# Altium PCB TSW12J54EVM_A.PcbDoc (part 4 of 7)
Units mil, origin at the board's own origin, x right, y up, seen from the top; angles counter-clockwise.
Board outline 6301 x 2680 mil, 10 copper layers (Top Layer - L1, Gnd-Plane - L2, Signals - L3, Gnd-Plane - L4, Pwr Plane - L5, Signals - L6, Gnd-Plane - L7, Signals - L8, Gnd-Plane - L9, Bottom Layer - L10), stack 57.8 mil thick; 650 components, 374 nets, 2074 pads, 1402 vias.
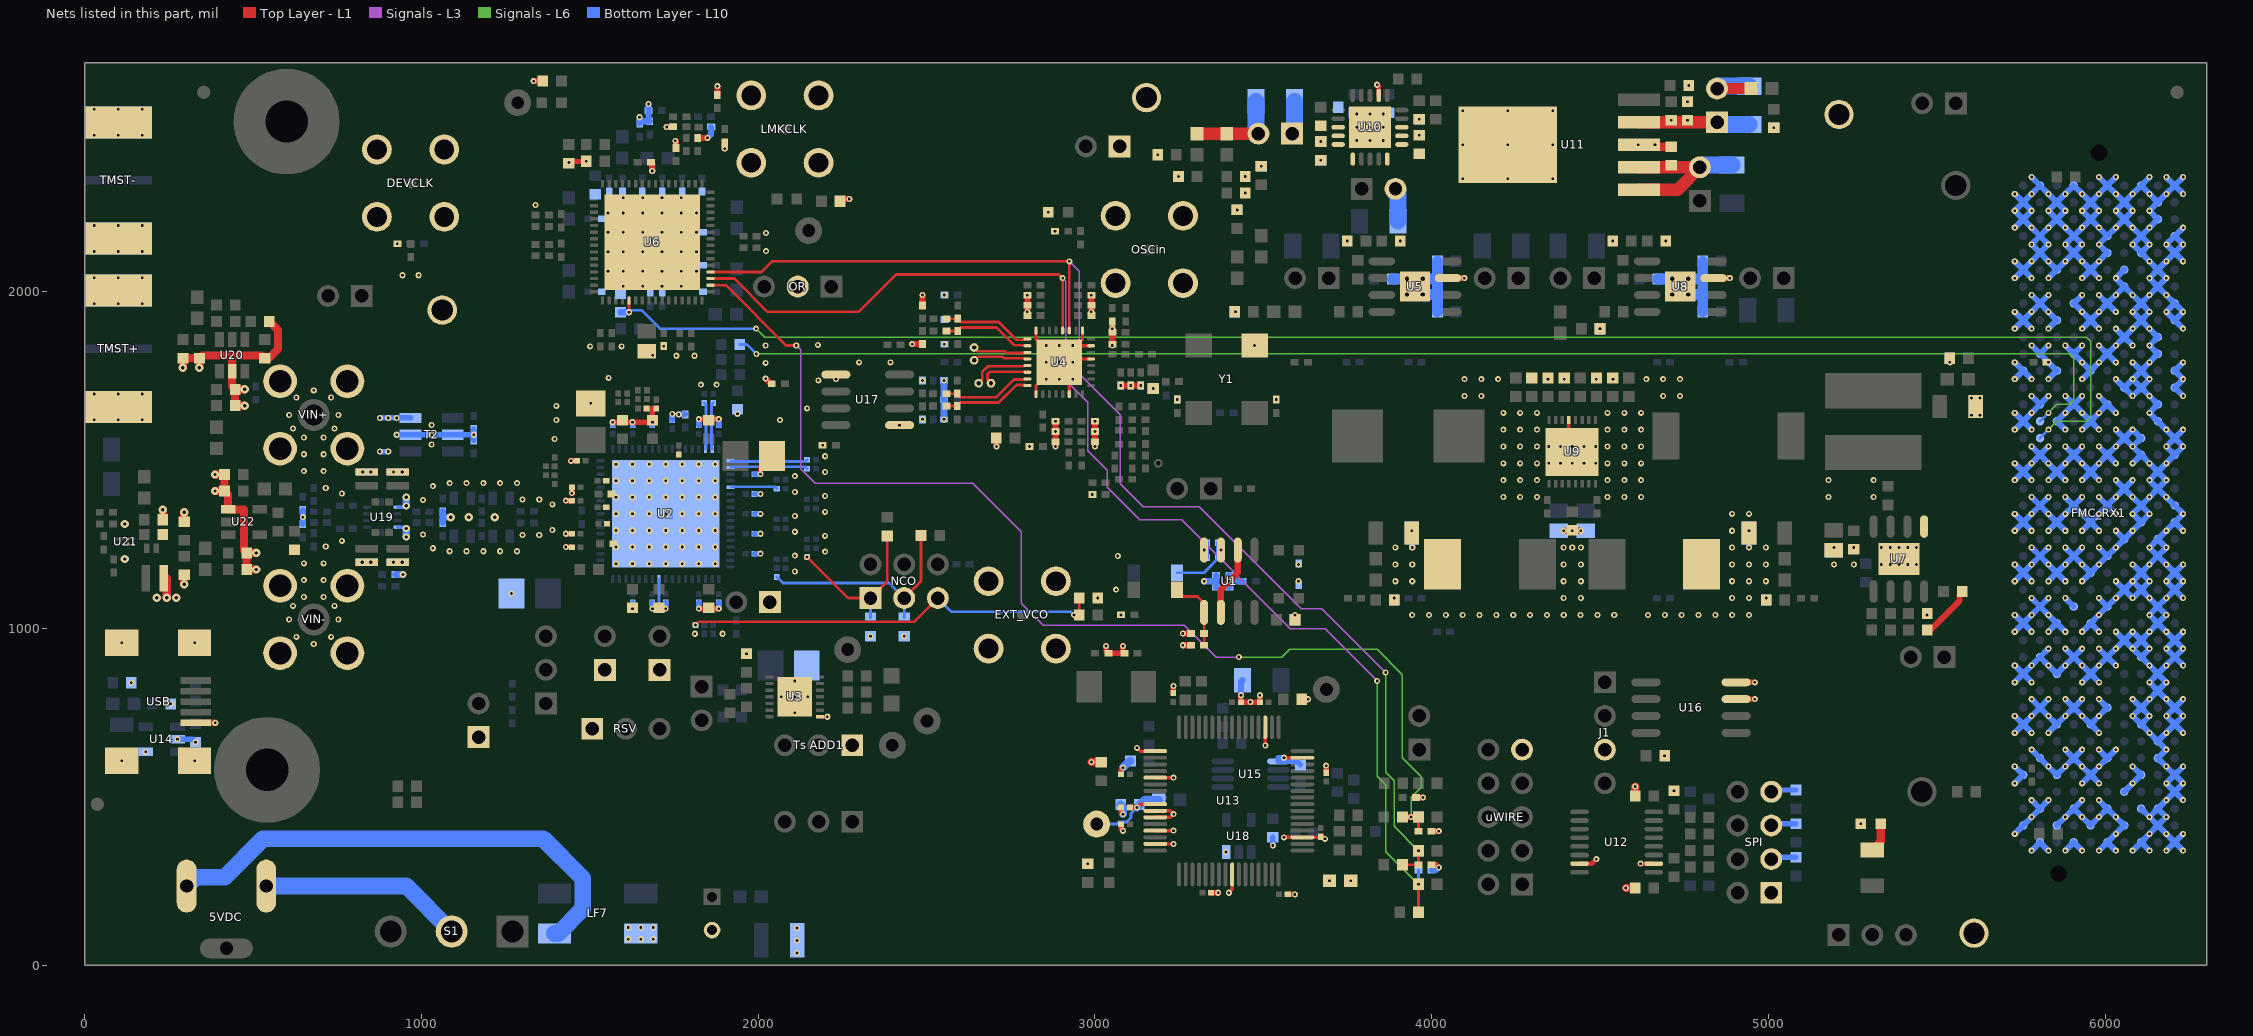
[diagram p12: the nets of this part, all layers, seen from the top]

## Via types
v1: diameter 18, hole 8, Top Layer - L1 to Bottom Layer - L10, tented both sides, 1120 vias
v2: diameter 19.68, hole 7.87, Top Layer - L1 to Bottom Layer - L10, 99 vias
v3: diameter 18, hole 8, Top Layer - L1 to Bottom Layer - L10, tented bottom, 42 vias
v4: diameter 18, hole 8, Top Layer - L1 to Bottom Layer - L10, tented top, 36 vias
v5: diameter 25, hole 10, Top Layer - L1 to Bottom Layer - L10, tented both sides, 32 vias
v6: diameter 21.46, hole 10, Top Layer - L1 to Bottom Layer - L10, tented both sides, 26 vias
v7: diameter 18, hole 8.01, Top Layer - L1 to Bottom Layer - L10, tented both sides, 16 vias
v8: diameter 18, hole 8.01, Top Layer - L1 to Bottom Layer - L10, tented bottom, 16 vias
v9: diameter 25.98, hole 12.99, Top Layer - L1 to Bottom Layer - L10, tented top, 8 vias
v10: diameter 19.68, hole 7.87, Top Layer - L1 to Bottom Layer - L10, tented top, 5 vias
v11: diameter 126, hole 106, Top Layer - L1 to Bottom Layer - L10, tented top, 2 vias

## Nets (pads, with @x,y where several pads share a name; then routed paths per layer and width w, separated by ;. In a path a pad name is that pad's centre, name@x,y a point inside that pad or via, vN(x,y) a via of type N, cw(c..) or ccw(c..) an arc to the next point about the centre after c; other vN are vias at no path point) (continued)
GND: 12V.2 "Ts ADD1.1" C2.2 C8.2 C11.2 C16.1 C18.1 C19.1 C24.2 C25.2 C27.2 C39.2 C40.2 C41.1 C42.1 C43.1 C44.1 C45.1 C46.1 C47.1 C48.2 C49.2 C50.2 C51.1 C52.1 C53.1 C54.1 C55.1 C56.1 C57.1 C58.1 C59.2 C60.2 C61.2 C62.1 C63.1 C64.1 C65.1 C66.1 C67.1 C68.1 C69.1 C70.1 C71.1 C72.2 C73.1 C74.1 C77.2 C78.2 C79.2 C80.2 C81.2 C82.2 C85.1 C88.2 C102.2 C103.2 C104.2 C105.2 C106.2 C107.2 C108.2 C109.2 C110.2 C111.2 C114.1 C115.2 C116.2 C120.2 C121.2 C122.2 C124.2 C125.2 C126.2 C127.2 C128.2 C129.2 C130.2 C143.2 C144.2 C145.2 C146.2 C147.2 C150.2 C151.2 C152.2 C153.2 C155.2 C156.1 C157.1 C158.2 C159.2 C160.2 C161.2 C162.2 C163.2 C164.2 C165.2 C166.2 C167.2 C168.2 C171.2 C172.2 C173.2 C176.2 C177.2 C178.2 C179.2 C180.2 C181.2 C182.2 C183.2 C184.2 C185.2 C186.2 C187.2 C188.2 C189.2 C190.2 C191.2 C193.2 C194.2 C195.2 C196.2 C197.2 C198.2 C199.2 C202.2 C203.2 C204.2 C206.2 C207.2 C208.2 C209.2 C213.2 C215.2 C218.2 C228.2 C229.2 C230.2 C231.1 C232.2 C233.2 C234.2 C235.1 C236.2 C237.2 C238.2 C239.2 C240.2 C241.2 C242.2 C243.2 C250.1 C251.1 C252.2 C253.2 C254.2 C255.2 C256.2 C257.2 C258.1 C259.1 C260.1 C261.2 C264.1 C265.2 C266.2 C267.1 C268.2 C269.1 C270.1 C271.2 C272.1 C276.2 C277.2 C278.2 C280.2 C281.2 C282.2 C283.2 C284.1 C285.1 C287.2 C288.2 C289.2 C290.2 C291.2 C292.1 D11.2 D12.2 DEVCLK.2 DEVCLK.3 DEVCLK.4 DEVCLK.5 EXT_Vcmo.1 EXT_VCO.2 EXT_VCO.3 EXT_VCO.4 EXT_VCO.5 FMC_RX1.A1 FMC_RX1.A4 FMC_RX1.A5 FMC_RX1.A8 FMC_RX1.A9 FMC_RX1.A12 FMC_RX1.A13 FMC_RX1.A16 FMC_RX1.A17 FMC_RX1.A20 FMC_RX1.A21 FMC_RX1.A24 FMC_RX1.A25 FMC_RX1.A28 FMC_RX1.A29 FMC_RX1.A32 FMC_RX1.A33 FMC_RX1.A36 FMC_RX1.A37 FMC_RX1.A40 FMC_RX1.B2 FMC_RX1.B3 FMC_RX1.B6 FMC_RX1.B7 FMC_RX1.B10 FMC_RX1.B11 FMC_RX1.B14 FMC_RX1.B15 FMC_RX1.B18 FMC_RX1.B19 FMC_RX1.B22 FMC_RX1.B23 FMC_RX1.B26 FMC_RX1.B27 FMC_RX1.B30 FMC_RX1.B31 FMC_RX1.B34 FMC_RX1.B35 FMC_RX1.B38 FMC_RX1.B39 FMC_RX1.C1 FMC_RX1.C4 FMC_RX1.C5 FMC_RX1.C8 FMC_RX1.C9 FMC_RX1.C12 FMC_RX1.C13 FMC_RX1.C16 FMC_RX1.C17 FMC_RX1.C20 FMC_RX1.C21 FMC_RX1.C24 FMC_RX1.C25 FMC_RX1.C28 FMC_RX1.C29 FMC_RX1.C32 FMC_RX1.C33 FMC_RX1.C36 FMC_RX1.C38 FMC_RX1.C40 FMC_RX1.D2 FMC_RX1.D3 FMC_RX1.D6 FMC_RX1.D7 FMC_RX1.D10 FMC_RX1.D13 FMC_RX1.D16 FMC_RX1.D19 FMC_RX1.D22 FMC_RX1.D25 FMC_RX1.D28 FMC_RX1.D37 FMC_RX1.D39 FMC_RX1.E1 FMC_RX1.E4 FMC_RX1.E5 FMC_RX1.E8 FMC_RX1.E11 FMC_RX1.E14 FMC_RX1.E17 FMC_RX1.E20 FMC_RX1.E23 FMC_RX1.E26 FMC_RX1.E29 FMC_RX1.E32 FMC_RX1.E35 FMC_RX1.E38 FMC_RX1.E40 FMC_RX1.F2 FMC_RX1.F3 FMC_RX1.F6 FMC_RX1.F9 FMC_RX1.F12 FMC_RX1.F15 FMC_RX1.F18 FMC_RX1.F21 FMC_RX1.F24 FMC_RX1.F27 FMC_RX1.F30 FMC_RX1.F33 FMC_RX1.F36 FMC_RX1.F39 FMC_RX1.G1 FMC_RX1.G4 FMC_RX1.G5 FMC_RX1.G8 FMC_RX1.G11 FMC_RX1.G14 FMC_RX1.G17 FMC_RX1.G20 FMC_RX1.G23 FMC_RX1.G26 FMC_RX1.G29 FMC_RX1.G32 FMC_RX1.G35 FMC_RX1.G38 FMC_RX1.G40 FMC_RX1.H2 FMC_RX1.H3 FMC_RX1.H6 FMC_RX1.H9 FMC_RX1.H12 FMC_RX1.H15 FMC_RX1.H18 FMC_RX1.H21 FMC_RX1.H24 FMC_RX1.H27 FMC_RX1.H30 FMC_RX1.H33 FMC_RX1.H36 FMC_RX1.H39 FMC_RX1.J1 FMC_RX1.J4 FMC_RX1.J5 FMC_RX1.J8 FMC_RX1.J11 FMC_RX1.J14 FMC_RX1.J17 FMC_RX1.J20 FMC_RX1.J23 FMC_RX1.J26 FMC_RX1.J29 FMC_RX1.J32 FMC_RX1.J35 FMC_RX1.J38 FMC_RX1.J40 FMC_RX1.K2 FMC_RX1.K3 FMC_RX1.K6 FMC_RX1.K9 FMC_RX1.K12 FMC_RX1.K15 FMC_RX1.K18 FMC_RX1.K21 FMC_RX1.K24 FMC_RX1.K27 FMC_RX1.K30 FMC_RX1.K33 FMC_RX1.K36 FMC_RX1.K39 GND1.1 GND2.1 GND3.1 GND.1 J1.3 L23.2 L37.2 LD.2 LF2.2 LF3.1 LF7.4 LMKCLK.2 LMKCLK.3 LMKCLK.4 LMKCLK.5 OR.2 OSCin.2 OSCin.3 OSCin.4 OSCin.5 R2.2 R3.1 R4.1 R5.1 R6.1 R10.2 R11.1 R12.1 R22.2 R23.2 R24.1 R26.1 R29.1 R30.1 R33.1 R36.1 R37.1 R45.1 R49.1 R50.2 R51.1 R56.1 R65.1 R76.1 R77.1 R86.1 R87.1 R88.1 R89.1 R90.1 R96.1 R104.1 R116.1 R122.1 R128.1 R129.1 R135.1 R139.1 R140.1 R141.1 R147.2 R152.2 R153.1 R158.1 R159.1 R165.1 R168.1 R172.1 R177.1 Ri+.1 RSV.1 SPI.1 SPI.3 SPI.5 SPI.7 T2.1 T2.2 T2.5 TMST+.2 TMST+.3 TMST+.4 TMST+.5 TMST-.2 TMST-.3 TMST-.4 TMST-.5 U1.4 U2.61 U2.69 U3.8 U3.15 U4.1 U4.8 U4.17 U4.22 U4.29 U4.31 U4.33 U5.3 U5.9 U6.65 U7.5 U7.9 U8.3 U8.9 U9.5 U9.17 U10.12 U10.21 U11.3 U11.6 U12.7 U12.10 U16.3 U16.4 U17.1 U17.5 U18.3 U19.11 U19.14 U20.2 U21.C1 U21.C2 U22.1 uWIRE.9 VA12.1 VA19.1 Vbg.1 VD12.1 VIN+.2 VIN+.3 VIN+.4 VIN+.5 VIN-.2 VIN-.3 VIN-.4 VIN-.5 Y1.2 | length 25734.7
  Top Layer - L1 w9: U3.8@2183.08,737.7 v1(2205.28,737.7)
  Top Layer - L1 w9.45: U4.17@2825.34,1695.51 2825.34,1721.1 v2(2894.24,1790) ; U4.8@2825.34,1884.49 2825.34,1858.9 v2(2894.24,1790) ; U4.33@2904.08,1799.84 U4.29@2988.72,1799.84 ; U4.22@2923.76,1695.51 U4.33@2923.76,1760.47 ; U4.33@2943.45,1839.21 U4.31@2988.72,1839.21 ; U4.1@2963.13,1884.49 2963.13,1858.9 v2(2894.24,1790)
  Top Layer - L1 w10: U9.5@4407.16,1618.49 4407.16,1553.53 U9.17@4417,1543.68
  Top Layer - L1 w11.02: v2(2894.24,1790) U4.33@2923.76,1760.47
  Top Layer - L1 w13: U12.7@4438.76,301.55 4475.03,301.55 v1(4488.48,315) ; v1(4619.68,301.55) U12.10@4659.24,301.55
  Top Layer - L1 w13.5: v1(3837.77,2614.17) 3842.27,2609.67 U10.12@3842.27,2582.49
  Top Layer - L1 w15: v1(1438.3,2383.18) 1441.86,2386.74 v1(1489.74,2386.74)
  Top Layer - L1 w16: v1(1429.03,1241.58) C51.1@1446.65,1241.57 ; v1(1429.03,1280.95) C41.1@1446.65,1280.94 ; v1(1429.03,1379.37) C42.1@1446.65,1379.37 ; v1(1444.03,1497.48) C44.1@1461.65,1497.48 ; v1(1446.65,1401.47) C54.1@1446.65,1418.74 ; v1(1567.91,1612) v1(1686.02,1612) ; R22.2@1668.99,1653 R23.2@1697,1653.01 ; v1(1686.02,1058.65) v1(1725.39,1058.65) ; C50.2@1686.02,1618.3 1686.02,1653 ; v1(1823.81,1058.65) v1(1882.87,1058.65) ; v1(1823.81,1621.35) v1(1882.87,1621.35) ; v1(2006.74,1458.11) 2006.74,1477.62 C72.2@2040.52,1511.4
  Top Layer - L1 w16.5: R116.1@3952.93,498 v1(3973.98,498) ; R128.1@3999.81,298 4012.87,298 v1(4020.87,290) ; R104.1@3999.81,398 v1(4020.87,398) ; U16.3@4903.86,790 v1(4959.16,790) ; U16.4@4903.86,840 v1(4959.16,840)
  Top Layer - L1 w18: v1(1333.3,2625) R45.1@1360.94,2625 ; C85.1@1681.68,2384 1685.56,2380.13 v1(1685.56,2358.32) ; v1(1728.43,2489) R50.2@1747.3,2489 ; v1(1754.16,2447.5) 1756,2445.65 C88.2@1756,2426.69 ; C114.1@1820.67,2456.68 v1(1849.54,2456.69) ; C259.1@1878.91,2584.24 v1(1878.91,2610.11) ; v1(1900.67,2424.26) R51.1@1900.67,2443.13 ; v1(2022.36,1741.48) 2037.84,1726 C215.2@2040.31,1726 ; v1(2230.84,1740) U17.5@2230.84,1753.5 ; R56.1@2243.06,2274.95 v1(2270.7,2274.95) ; v1(2457.23,1843.81) R36.1@2488.05,1843.81 ; R29.1@2488.05,1959.18 v1(2488.05,1990) ; v1(2707.44,1540) R152.2@2707.44,1565 ; C257.2@2799.35,1929.09 C256.2@2799.35,1959.09 v1(2799.35,1989.09) ; v1(2882.55,1540) C243.2@2882.55,1554.68 v1(2882.55,1614.68) ; C254.2@2989.12,1929.09 C253.2@2989.12,1959.09 v1(2989.12,1989.09) ; v1(2999.92,1540) C240.2@2999.92,1554.68 v1(2999.92,1614.68) ; v1(3076.33,1721.1) v1(3136.33,1721.1) ; v1(3260.82,950) R11.1@3284.63,950 ; v1(3260.82,985) C8.2@3284.63,985 ; U5.3@4048.43,2040 v1(4096.8,2040) ; v1(4391.47,1290) v1(4442.53,1290) ; U8.3@4836.43,2040 v1(4884.8,2040) ; R76.1@5470.56,995 5480,995 5567,1082 5567,1101.98 C162.2@5574.56,1109.54
  Top Layer - L1 w19.68: C251.1@3051.65,1844 R30.1@3051.65,1911.41
  Top Layer - L1 w24: C282.2@232.29,1322.99 v5(232.29,1352.22) ; v5(291.99,1774.4) C280.2@291.99,1802.65 C281.2@340.99,1802.65 ; v5(295.73,1131.18) C284.1@295.73,1159.43 ; C285.1@295.73,1316.55 v5(295.73,1344.8) ; v5(340.99,1774.4) C281.2@340.99,1802.65 ; v5(387.19,1408) C289.2@415.44,1408 ; v5(387.19,1457) C290.2@415.44,1457 C289.2@415.44,1408 ; v5(475.1,1661.52) C276.2@446.85,1661.52 C277.2@446.85,1709.52 ; v5(475.1,1709.52) C277.2@446.85,1709.52 ; v5(509.44,1175) C287.2@481.19,1175 C288.2@481.19,1224 ; v5(509.44,1224) C288.2@481.19,1224 ; R172.1@548.55,1911.52 573.99,1886.08 573.99,1829.45 547.19,1802.65 C278.2@534.99,1802.65 527.12,1810.52 437.99,1810.52 ; v1(4576.37,229) R65.1@4604.12,229 ; C129.2@4604.12,502.06 v1(4604.12,530.79) ; U11.3@4615.22,2436 4621.13,2430.09 C196.2@4711,2430.09 ; C281.2@340.99,1802.65 348.87,1810.52 437.99,1810.52 ; C289.2@415.44,1408 426.07,1397.37 U22.1@426.07,1353.4 473.32,1353.4 473.32,1231.87 C288.2@481.19,1224 ; 437.99,1810.52 U20.2@437.99,1763.28 437.99,1718.38 C277.2@446.85,1709.52
  Top Layer - L1 w25: v5(243.59,1090.99) L37.2@243.59,1148.49
  Bottom Layer - L10 w9: 1705.7,1058.65 U2.61@1705.7,1147.09
  Bottom Layer - L10 w9.84: U19.14@928.89,1300.63 951.4,1300.63 v6(955.37,1296.66) ; U19.11@928.89,1359.68 951.4,1359.68 v6(955.37,1363.65)
  Bottom Layer - L10 w16: v1(876.58,1524.95) v1(901.58,1524.95) ; v1(876.58,1624.95) T2.1@968.06,1624.95 ; v1(926.58,1574.95) v1(1155.85,1574.95) ; C229.2@1155.85,1558.14 v1(1155.85,1574.95) ; C228.2@1155.85,1591.76 v1(1155.85,1574.95) ; C45.1@1567.91,1603.73 v1(1567.91,1612) ; v1(1626.96,1058.65) C47.1@1626.96,1076.27 ; C46.1@1626.96,1603.73 v1(1626.96,1612) ; C58.1@1686.01,1076.27 v1(1686.02,1058.65) v1(1725.39,1058.65) C57.1@1725.39,1076.27 ; C55.1@1686.02,1603.73 v1(1686.02,1612) ; C56.1@1745.07,1618.73 v1(1745.07,1636.35) ; v1(1764.16,1635.31) C16.1@1783,1635.31 ; v1(1823.81,1058.65) C62.1@1823.81,1076.27 ; C70.1@1823.81,1603.73 v1(1823.81,1621.35) ; v1(1882.87,1058.65) C63.1@1882.87,1076.27 ; C69.1@1882.87,1603.73 v1(1882.87,1621.35) ; C64.1@1989.12,1221.89 v1(2006.74,1221.89) ; C65.1@1989.12,1280.95 v1(2006.74,1280.94) ; C66.1@1989.12,1340 v1(2006.74,1340) ; C67.1@1989.12,1399.05 v1(2006.74,1399.05) ; C68.1@1989.12,1458.11 v1(2006.74,1458.11) ; SPI.3@5008,315 5013.12,320.12 R139.1@5081.44,320.12 ; SPI.5@5008,415 5013.12,420.12 R140.1@5081.44,420.12 ; SPI.7@5008,515 5013.12,520.12 R141.1@5081.44,520.12
  Bottom Layer - L10 w16.5: v1(3528,355.39) C213.2@3528,380.13 ; R129.1@3999.81,282 4012.87,282 v1(4020.87,290)
  Bottom Layer - L10 w18: R168.1@648,1309.35 v1(648,1330.16) Ri+.1@648,1350.97 ; C107.2@1647.92,2498.87 v1(1647.92,2517.74) ; C107.2@1647.92,2505.74 C104.2@1678.05,2505.74 1674.31,2509.47 C260.1@1674.32,2537.87 v1(1674.32,2556.74) ; v1(1728.43,2489) R159.1@1747.3,2489 ; v1(1849.54,2456.69) 1860.04,2467.19 R158.1@1860.04,2489 ; v1(3942,1240) C183.2@3942,1290 ; 4016.93,2040 v1(4096.8,2040) ; 4804.93,2040 v1(4884.8,2040) ; v1(4941.85,1240) v1(4941.85,1290) ; v1(5731,390) FMC_RX1.K39@5756,415 v1(5781,440) FMC_RX1.J38@5806,465 ; v1(5731,540) FMC_RX1.K36@5756,565 v1(5731,590) ; v1(5731,690) FMC_RX1.K33@5756,715 ; v1(5731,740) FMC_RX1.K33@5756,715 ; v1(5731,840) FMC_RX1.K30@5756,865 ; v1(5731,890) FMC_RX1.K30@5756,865 ; v1(5731,990) FMC_RX1.K27@5756,1015 ; v1(5731,1040) FMC_RX1.K27@5756,1015 ; v1(5731,1140) FMC_RX1.K24@5756,1165 ; v1(5731,1190) FMC_RX1.K24@5756,1165 ; v1(5731,1290) FMC_RX1.K21@5756,1315 ; v1(5731,1340) FMC_RX1.K21@5756,1315 ; v1(5731,1440) FMC_RX1.K18@5756,1465 ; v1(5731,1490) FMC_RX1.K18@5756,1465 ; v1(5731,1590) FMC_RX1.K15@5756,1615 ; v1(5731,1640) FMC_RX1.K15@5756,1615 ; v1(5731,1740) FMC_RX1.K12@5756,1765 ; v1(5731,1790) FMC_RX1.K12@5756,1765 ; v1(5731,1890) FMC_RX1.K9@5756,1915 ; v1(5731,1940) FMC_RX1.K9@5756,1915 ; v1(5731,2040) FMC_RX1.K6@5756,2065 ; v1(5731,2090) FMC_RX1.K6@5756,2065 ; v1(5731,2190) FMC_RX1.K3@5756,2215 ; v1(5731,2290) FMC_RX1.K2@5756,2265 ; v1(5781,340) FMC_RX1.J40@5806,365 v1(5831,340) ; v1(5781,490) FMC_RX1.J38@5806,465 ; v1(5781,640) FMC_RX1.J35@5806,615 v1(5831,590) FMC_RX1.H36@5856,565 v1(5881,590) FMC_RX1.G35@5906,615 ; v1(5781,690) FMC_RX1.K33@5756,715 ; v1(5781,790) FMC_RX1.J32@5806,765 ; v1(5781,840) FMC_RX1.K30@5756,865 ; v1(5781,990) FMC_RX1.K27@5756,1015 ; v1(5781,1090) FMC_RX1.J26@5806,1065 ; v1(5781,1140) FMC_RX1.K24@5756,1165 ; v1(5781,1240) FMC_RX1.J23@5806,1215 ; v1(5781,1290) FMC_RX1.K21@5756,1315 ; v1(5781,1390) FMC_RX1.J20@5806,1365 ; v1(5781,1440) FMC_RX1.K18@5756,1465 ; v1(5781,1540) FMC_RX1.J17@5806,1515 ; v1(5781,1590) FMC_RX1.K15@5756,1615 ; v1(5781,1690) FMC_RX1.J14@5806,1665 ; v1(5781,1740) FMC_RX1.K12@5756,1765 ; v1(5781,1840) FMC_RX1.J11@5806,1815 ; v1(5781,1890) FMC_RX1.K9@5756,1915 ; v1(5781,1990) FMC_RX1.J8@5806,1965 ; v1(5781,2040) FMC_RX1.K6@5756,2065 ; v1(5781,2340) FMC_RX1.J1@5806,2315 ; v1(5831,490) FMC_RX1.J38@5806,465 ; v1(5831,690) FMC_RX1.H33@5856,715 ; v1(5831,790) FMC_RX1.J32@5806,765 ; v1(5831,940) FMC_RX1.J29@5806,915 ; v1(5831,990) FMC_RX1.H27@5856,1015 ; v1(5831,1090) FMC_RX1.J26@5806,1065 ; v1(5831,1140) FMC_RX1.H24@5856,1165 ; v1(5831,1240) FMC_RX1.J23@5806,1215 ; v1(5831,1290) FMC_RX1.H21@5856,1315 ; v1(5831,1390) FMC_RX1.J20@5806,1365 ; v1(5831,1440) FMC_RX1.H18@5856,1465 ; v1(5831,1540) FMC_RX1.J17@5806,1515 ; v1(5831,1690) FMC_RX1.J14@5806,1665 ; v1(5831,1740) FMC_RX1.H12@5856,1765 v1(5831,1790) FMC_RX1.J11@5806,1815 ; v1(5831,1840) FMC_RX1.J11@5806,1815 ; v1(5831,1890) FMC_RX1.H9@5856,1915 v1(5831,1940) FMC_RX1.J8@5806,1965 ; v1(5831,1990) FMC_RX1.J8@5806,1965 ; v1(5831,2040) FMC_RX1.H6@5856,2065 ; FMC_RX1.H39@5856,415 v1(5881,440) FMC_RX1.G38@5906,465 ; v1(5881,340) FMC_RX1.G40@5906,365 v1(5931,340) ; v1(5881,640) FMC_RX1.G35@5906,615 ; v1(5881,790) FMC_RX1.G32@5906,765 ; v1(5881,940) FMC_RX1.G29@5906,915 ; v1(5881,990) FMC_RX1.H27@5856,1015 ; v1(5881,1090) FMC_RX1.G26@5906,1065 ; v1(5881,1140) FMC_RX1.H24@5856,1165 ; v1(5881,1240) FMC_RX1.G23@5906,1215 ; v1(5881,1290) FMC_RX1.H21@5856,1315 ; v1(5881,1390) FMC_RX1.G20@5906,1365 ; v1(5881,1440) FMC_RX1.H18@5856,1465 ; v1(5881,1540) FMC_RX1.G17@5906,1515 ; v1(5881,1590) FMC_RX1.H15@5856,1615 v1(5881,1640) FMC_RX1.G14@5906,1665 ; v1(5881,1690) FMC_RX1.G14@5906,1665 ; v1(5881,1840) FMC_RX1.G11@5906,1815 ; v1(5931,490) FMC_RX1.G38@5906,465 ; v1(5931,540) FMC_RX1.F36@5956,565 ; v1(5931,640) FMC_RX1.G35@5906,615 ; v1(5931,790) FMC_RX1.G32@5906,765 ; v1(5931,840) FMC_RX1.F30@5956,865 ; v1(5931,940) FMC_RX1.G29@5906,915 ; v1(5931,990) FMC_RX1.F27@5956,1015 ; v1(5931,1140) FMC_RX1.F24@5956,1165 ; v1(5931,1240) FMC_RX1.G23@5906,1215 ; v1(5931,1290) FMC_RX1.F21@5956,1315 ; v1(5931,1390) FMC_RX1.G20@5906,1365 ; v1(5931,1440) FMC_RX1.F18@5956,1465 ; v1(5931,1540) FMC_RX1.G17@5906,1515 ; v1(5931,1590) FMC_RX1.F15@5956,1615 ; v1(5931,1690) FMC_RX1.G14@5906,1665 ; v1(5931,1740) FMC_RX1.F12@5956,1765 ; v1(5931,1840) FMC_RX1.G11@5906,1815 ; v1(5931,1890) FMC_RX1.F9@5956,1915 ; v1(5931,1990) FMC_RX1.G8@5906,1965 v1(5931,1940) FMC_RX1.F9@5956,1915 ; v1(5931,2040) FMC_RX1.F6@5956,2065 ; FMC_RX1.F9@5954,1913 v1@5979,1938 ; v1(5981,340) FMC_RX1.E40@6006,365 ; v1(5981,490) FMC_RX1.E38@6006,465 ; v1(5981,540) FMC_RX1.F36@5956,565 ; v1(5981,640) FMC_RX1.E35@6006,615 ; v1(5981,690) FMC_RX1.F33@5956,715 ; v1(5981,790) FMC_RX1.E32@6006,765 v1(5981,740) FMC_RX1.F33@5956,715 ; v1(5981,840) FMC_RX1.F30@5956,865 ; v1(5981,940) FMC_RX1.E29@6006,915 ; v1(5981,990) FMC_RX1.F27@5956,1015 ; v1(5981,1090) FMC_RX1.E26@6006,1065 ; v1(5981,1240) FMC_RX1.E23@6006,1215 ; v1(5981,1290) FMC_RX1.F21@5956,1315 ; v1(5981,1390) FMC_RX1.E20@6006,1365 ; v1(5981,1440) FMC_RX1.F18@5956,1465 ; v1(5981,1540) FMC_RX1.E17@6006,1515 ; v1(5981,1590) FMC_RX1.F15@5956,1615 ; v1(5981,1690) FMC_RX1.E14@6006,1665 ; v1(5981,1840) FMC_RX1.E11@6006,1815 ; v1(5981,1890) FMC_RX1.F9@5956,1915 ; v1(5981,1940) FMC_RX1.E8@6006,1965 ; v1(5981,1990) FMC_RX1.E8@6006,1965 ; v1(5981,2040) FMC_RX1.F6@5956,2065 ; v1(5981,2340) FMC_RX1.E1@6006,2315 ; v1(6031,340) FMC_RX1.E40@6006,365 ; v1(6031,640) FMC_RX1.E35@6006,615 ; v1(6031,890) FMC_RX1.E29@6006,915 ; v1(6031,990) FMC_RX1.D28@6056,965 ; v1(6031,1140) FMC_RX1.D25@6056,1115 ; v1(6031,1290) FMC_RX1.D22@6056,1265 ; v1(6031,1340) FMC_RX1.E20@6006,1365 ; v1(6031,1440) FMC_RX1.D19@6056,1415 ; v1(6031,1490) FMC_RX1.E17@6006,1515 ; v1(6031,1590) FMC_RX1.D16@6056,1565 ; v1(6031,1640) FMC_RX1.E14@6006,1665 ; v1(6031,1740) FMC_RX1.D13@6056,1715 ; v1(6031,1790) FMC_RX1.E11@6006,1815 ; v1(6031,1890) FMC_RX1.D10@6056,1865 ; v1(6031,1940) FMC_RX1.E8@6006,1965 ; v1(6031,2340) FMC_RX1.E1@6006,2315 ; FMC_RX1.D37@6056,515 v1(6081,540) FMC_RX1.C36@6106,565 v1(6081,590) ; FMC_RX1.D6@6056,2065 v1(6031,2040) FMC_RX1.D7@6056,2015 ; v1(6081,340) FMC_RX1.C40@6106,365 ; v1(6081,790) FMC_RX1.C32@6106,765 ; v1(6081,1140) FMC_RX1.D25@6056,1115 ; v1(6081,1190) FMC_RX1.C24@6106,1165 ; v1(6081,1440) FMC_RX1.D19@6056,1415 ; v1(6081,1490) FMC_RX1.C17@6106,1515 ; v1(6081,1790) FMC_RX1.C12@6106,1765 ; v1(6081,1840) FMC_RX1.D10@6056,1865 ; FMC_RX1.C38@6106,465 v1(6131,440) ; FMC_RX1.C25@6107,1115 6082,1140 FMC_RX1.C24@6107,1165 ; v1(6131,340) FMC_RX1.C40@6106,365 ; v1(6131,1440) FMC_RX1.B18@6156,1465 ; v1(6131,2340) FMC_RX1.C1@6106,2315 ; v1@6135,1436 FMC_RX1.B19@6160,1411 ; v1(6181,340) FMC_RX1.A40@6206,365 ; v1(6181,2340) FMC_RX1.A1@6206,2315 ; v1(6231,340) FMC_RX1.A40@6206,365 ; v1(6231,390) FMC_RX1.A40@6206,365 ; v1(6231,490) FMC_RX1.A37@6206,515 ; v1(6231,590) FMC_RX1.A36@6206,565 ; v1(6231,690) FMC_RX1.A33@6206,715 ; v1(6231,790) FMC_RX1.A32@6206,765 ; v1(6231,890) FMC_RX1.A29@6206,915 ; v1(6231,990) FMC_RX1.A28@6206,965 ; v1(6231,1090) FMC_RX1.A25@6206,1115 ; v1(6231,1190) FMC_RX1.A24@6206,1165 ; v1(6231,1290) FMC_RX1.A21@6206,1315 ; v1(6231,1590) FMC_RX1.A16@6206,1565 ; v1(6231,1690) FMC_RX1.A13@6206,1715 v1(6231,1740) FMC_RX1.A12@6206,1765 v1(6231,1790) ; v1(6231,1890) FMC_RX1.A9@6206,1915 ; v1(6231,2090) FMC_RX1.A5@6206,2115 ; v1(6231,2190) FMC_RX1.A4@6206,2165 ; v1(6231,2290) FMC_RX1.A1@6206,2315 ; v1(6231,2340) FMC_RX1.A1@6206,2315 ; FMC_RX1.K33@5756,715 v1(5781,740) FMC_RX1.J32@5806,765 ; FMC_RX1.K30@5756,865 v1(5781,890) FMC_RX1.J29@5806,915 ; FMC_RX1.K27@5756,1015 v1(5781,1040) FMC_RX1.J26@5806,1065 ; FMC_RX1.K24@5756,1165 v1(5781,1190) FMC_RX1.J23@5806,1215 ; FMC_RX1.K21@5756,1315 v1(5781,1340) FMC_RX1.J20@5806,1365 ; FMC_RX1.K18@5756,1465 v1(5781,1490) FMC_RX1.J17@5806,1515 ; FMC_RX1.K15@5756,1615 v1(5781,1640) FMC_RX1.J14@5806,1665 ; FMC_RX1.K9@5756,1915 v1(5781,1940) FMC_RX1.J8@5806,1965 ; FMC_RX1.K6@5756,2065 v1(5781,2090) FMC_RX1.J5@5806,2115 ; FMC_RX1.K3@5756,2215 v1(5731,2240) FMC_RX1.K2@5756,2265 ; FMC_RX1.K3@5756,2215 v1(5781,2190) FMC_RX1.J4@5806,2165 ; FMC_RX1.K3@5756,2215 v1(5781,2240) FMC_RX1.K2@5756,2265 ; FMC_RX1.K2@5756,2265 v1(5781,2290) FMC_RX1.J1@5806,2315 ; FMC_RX1.J32@5806,765 v1(5831,740) FMC_RX1.H33@5856,715 ; FMC_RX1.J29@5806,915 v1(5831,890) FMC_RX1.H30@5856,865 v1(5881,890) FMC_RX1.G29@5906,915 ; FMC_RX1.J26@5806,1065 v1(5831,1040) FMC_RX1.H27@5856,1015 ; FMC_RX1.J23@5806,1215 v1(5831,1190) FMC_RX1.H24@5856,1165 ; FMC_RX1.J20@5806,1365 v1(5831,1340) FMC_RX1.H21@5856,1315 ; FMC_RX1.J17@5806,1515 v1(5831,1490) FMC_RX1.H18@5856,1465 ; FMC_RX1.J5@5806,2115 v1(5831,2090) FMC_RX1.H6@5856,2065 ; FMC_RX1.J5@5806,2115 v1(5781,2140) FMC_RX1.J4@5806,2165 ; FMC_RX1.J5@5806,2115 v1(5831,2140) FMC_RX1.J4@5806,2165 ; FMC_RX1.J4@5806,2165 v1(5831,2190) FMC_RX1.H3@5856,2215 ; FMC_RX1.J1@5806,2315 v1(5831,2290) FMC_RX1.H2@5856,2265 ; FMC_RX1.H33@5856,715 v1(5881,740) FMC_RX1.G32@5906,765 ; FMC_RX1.H24@5856,1165 v1(5881,1190) FMC_RX1.G23@5906,1215 ; FMC_RX1.H21@5856,1315 v1(5881,1340) FMC_RX1.G20@5906,1365 ; FMC_RX1.H18@5856,1465 v1(5881,1490) FMC_RX1.G17@5906,1515 ; FMC_RX1.H6@5856,2065 v1(5881,2090) FMC_RX1.G5@5906,2115 ; FMC_RX1.H3@5856,2215 v1(5881,2240) FMC_RX1.H2@5856,2265 ; FMC_RX1.H3@5856,2215 v1(5881,2190) FMC_RX1.G4@5906,2165 ; FMC_RX1.H3@5856,2215 v1(5831,2240) FMC_RX1.H2@5856,2265 ; FMC_RX1.H2@5856,2265 v1(5881,2290) FMC_RX1.G1@5906,2315 v1(5931,2290) FMC_RX1.F2@5956,2265 ; FMC_RX1.G38@5906,465 v1(5931,440) FMC_RX1.F39@5956,415 v1(5981,440) FMC_RX1.E38@6006,465 ; FMC_RX1.G35@5906,615 v1(5931,590) FMC_RX1.F36@5956,565 ; FMC_RX1.G32@5906,765 v1(5931,740) FMC_RX1.F33@5956,715 ; FMC_RX1.G29@5906,915 v1(5931,890) FMC_RX1.F30@5956,865 ; FMC_RX1.G23@5906,1215 v1(5931,1190) FMC_RX1.F24@5956,1165 ; FMC_RX1.G20@5906,1365 v1(5931,1340) FMC_RX1.F21@5956,1315 ; FMC_RX1.G17@5906,1515 v1(5931,1490) FMC_RX1.F18@5956,1465 ; FMC_RX1.G14@5906,1665 v1(5931,1640) FMC_RX1.F15@5956,1615 ; FMC_RX1.G11@5906,1815 v1(5931,1790) FMC_RX1.F12@5956,1765 ; FMC_RX1.G5@5906,2115 v1(5931,2090) FMC_RX1.F6@5956,2065 ; FMC_RX1.G5@5906,2115 v1(5881,2140) FMC_RX1.G4@5906,2165 ; FMC_RX1.G5@5906,2115 v1(5931,2140) FMC_RX1.G4@5906,2165 ; FMC_RX1.G4@5906,2165 v1(5931,2190) FMC_RX1.F3@5956,2215 ; FMC_RX1.F36@5956,565 v1(5981,590) FMC_RX1.E35@6006,615 ; FMC_RX1.F30@5956,865 v1(5981,890) FMC_RX1.E29@6006,915 ; FMC_RX1.F27@5956,1015 v1(5981,1040) FMC_RX1.E26@6006,1065 ; FMC_RX1.F24@5956,1165 v1(5981,1190) FMC_RX1.E23@6006,1215 ; FMC_RX1.F21@5956,1315 v1(5981,1340) FMC_RX1.E20@6006,1365 ; FMC_RX1.F18@5956,1465 v1(5981,1490) FMC_RX1.E17@6006,1515 ; FMC_RX1.F15@5956,1615 v1(5981,1640) FMC_RX1.E14@6006,1665 ; FMC_RX1.F12@5956,1765 v1(5981,1790) FMC_RX1.E11@6006,1815 ; FMC_RX1.F6@5956,2065 v1(5981,2090) FMC_RX1.E5@6006,2115 v1(5981,2140) FMC_RX1.E4@6006,2165 ; FMC_RX1.F3@5956,2215 v1(5981,2190) FMC_RX1.E4@6006,2165 ; FMC_RX1.F3@5956,2215 v1(5931,2240) FMC_RX1.F2@5956,2265 ; FMC_RX1.F3@5956,2215 v1(5981,2240) FMC_RX1.F2@5956,2265 ; FMC_RX1.F2@5956,2265 v1(5981,2290) FMC_RX1.E1@6006,2315 ; FMC_RX1.E40@6006,365 v1(6031,390) FMC_RX1.D39@6056,415 v1(6031,440) FMC_RX1.E38@6006,465 ; FMC_RX1.E29@6006,915 v1(6031,940) FMC_RX1.D28@6056,965 ; FMC_RX1.E26@6006,1065 v1(6031,1090) FMC_RX1.D25@6056,1115 ; FMC_RX1.E23@6006,1215 v1(6031,1240) FMC_RX1.D22@6056,1265 ; FMC_RX1.E20@6006,1365 v1(6031,1390) FMC_RX1.D19@6056,1415 ; FMC_RX1.E17@6006,1515 v1(6031,1540) FMC_RX1.D16@6056,1565 ; FMC_RX1.E11@6006,1815 v1(6031,1840) FMC_RX1.D10@6056,1865 ; FMC_RX1.E8@6006,1965 v1(6031,1990) FMC_RX1.D7@6056,2015 ; FMC_RX1.E4@6006,2165 v1(6031,2190) FMC_RX1.D3@6056,2215 ; FMC_RX1.E1@6006,2315 v1(6031,2290) FMC_RX1.D2@6056,2265 ; FMC_RX1.D28@6056,965 v1(6081,940) ; FMC_RX1.D28@6056,965 v1(6081,990) FMC_RX1.C28@6106,965 ; FMC_RX1.D25@6056,1115 v1(6081,1090) FMC_RX1.C25@6106,1115 ; FMC_RX1.D22@6056,1265 v1(6081,1290) FMC_RX1.C21@6106,1315 ; FMC_RX1.D19@6056,1415 v1(6081,1390) FMC_RX1.C20@6106,1365 ; FMC_RX1.D16@6056,1565 v1(6081,1540) ; FMC_RX1.D16@6056,1565 v1(6081,1590) FMC_RX1.C16@6106,1565 v1(6081,1540) ; FMC_RX1.D13@6056,1715 v1(6081,1740) ; FMC_RX1.D13@6056,1715 v1(6081,1690) FMC_RX1.C13@6106,1715 ; FMC_RX1.D10@6056,1865 v1(6081,1890) FMC_RX1.C9@6106,1915 ; FMC_RX1.D7@6056,2015 v1(6081,1990) FMC_RX1.C8@6106,1965 ; FMC_RX1.D3@6056,2215 v1(6081,2240) FMC_RX1.D2@6056,2265 ; FMC_RX1.D3@6056,2215 v1(6081,2190) FMC_RX1.C4@6106,2165 ; FMC_RX1.D3@6056,2215 v1(6031,2240) FMC_RX1.D2@6056,2265 ; FMC_RX1.D2@6056,2265 v1(6081,2290) FMC_RX1.C1@6106,2315 ; v1(6081,940) FMC_RX1.C28@6106,965 ; v1(6081,940) FMC_RX1.C29@6106,915 ; v1(6081,1540) FMC_RX1.C17@6106,1515 ; v1(6081,1740) FMC_RX1.C13@6106,1715 ; v1(6081,1740) FMC_RX1.C12@6106,1765 ; FMC_RX1.C40@6106,365 v1(6131,390) FMC_RX1.B39@6156,415 ; FMC_RX1.C33@6106,715 v1(6131,690) FMC_RX1.B34@6156,665 ; FMC_RX1.C33@6106,715 v1(6131,740) FMC_RX1.C32@6106,765 ; FMC_RX1.C33@6106,715 v1(6081,740) FMC_RX1.C32@6106,765 ; FMC_RX1.C32@6106,765 v1(6131,790) FMC_RX1.B31@6156,815 ; FMC_RX1.C29@6106,915 v1(6131,890) FMC_RX1.B30@6156,865 ; FMC_RX1.C29@6106,915 v1(6131,940) FMC_RX1.C28@6106,965 ; FMC_RX1.C28@6106,965 v1(6131,990) FMC_RX1.B27@6156,1015 ; FMC_RX1.C25@6106,1115 v1(6131,1090) FMC_RX1.B26@6156,1065 ; FMC_RX1.C25@6106,1115 v1(6131,1140) FMC_RX1.C24@6106,1165 ; FMC_RX1.C24@6106,1165 v1(6131,1190) FMC_RX1.B23@6156,1215 ; FMC_RX1.C21@6106,1315 v1(6081,1340) FMC_RX1.C20@6106,1365 ; FMC_RX1.C21@6106,1315 v1(6131,1340) FMC_RX1.C20@6106,1365 ; FMC_RX1.C20@6106,1365 v1(6131,1390) FMC_RX1.B19@6156,1415 ; FMC_RX1.C17@6106,1515 v1(6131,1490) FMC_RX1.B18@6156,1465 ; FMC_RX1.C13@6106,1715 v1(6131,1740) FMC_RX1.C12@6106,1765 ; FMC_RX1.C13@6106,1715 v1(6131,1690) FMC_RX1.B14@6156,1665 v1(6131,1640) FMC_RX1.B15@6156,1615 v1(6181,1590) FMC_RX1.A16@6206,1565 ; FMC_RX1.C12@6106,1765 v1(6131,1790) FMC_RX1.B11@6156,1815 v1(6131,1840) FMC_RX1.B10@6156,1865 v1(6131,1890) FMC_RX1.C9@6106,1915 ; FMC_RX1.C9@6106,1915 v1(6131,1940) FMC_RX1.C8@6106,1965 ; FMC_RX1.C9@6106,1915 v1(6081,1940) FMC_RX1.C8@6106,1965 ; FMC_RX1.C8@6106,1965 v1(6131,1990) FMC_RX1.B7@6156,2015 ; FMC_RX1.C5@6106,2115 v1(6131,2140) FMC_RX1.C4@6106,2165 ; FMC_RX1.C5@6106,2115 v1(6081,2140) FMC_RX1.C4@6106,2165 ; FMC_RX1.C5@6106,2115 v1(6131,2090) FMC_RX1.B6@6156,2065 ; FMC_RX1.C4@6106,2165 v1(6131,2190) FMC_RX1.B3@6156,2215 v1(6131,2240) FMC_RX1.B2@6156,2265 ; FMC_RX1.C1@6106,2315 v1(6131,2290) FMC_RX1.B2@6156,2265 ; v1(6131,440) FMC_RX1.B38@6156,465 ; v1(6131,440) FMC_RX1.B39@6156,415 ; FMC_RX1.B39@6156,415 v1(6181,440) FMC_RX1.B38@6156,465 ; FMC_RX1.B39@6156,415 v1(6181,390) FMC_RX1.A40@6206,365 ; FMC_RX1.B38@6156,465 v1(6181,490) FMC_RX1.A37@6206,515 ; FMC_RX1.B34@6156,665 v1(6181,690) FMC_RX1.A33@6206,715 ; FMC_RX1.B34@6156,665 v1(6181,640) FMC_RX1.B35@6156,615 v1(6181,590) FMC_RX1.A36@6206,565 ; FMC_RX1.B31@6156,815 v1(6131,840) FMC_RX1.B30@6156,865 ; FMC_RX1.B31@6156,815 v1(6181,840) FMC_RX1.B30@6156,865 ; FMC_RX1.B31@6156,815 v1(6181,790) FMC_RX1.A32@6206,765 ; FMC_RX1.B30@6156,865 v1(6181,890) FMC_RX1.A29@6206,915 ; FMC_RX1.B27@6156,1015 v1(6131,1040) FMC_RX1.B26@6156,1065 ; FMC_RX1.B27@6156,1015 v1(6181,990) FMC_RX1.A28@6206,965 ; FMC_RX1.B27@6156,1015 v1(6181,1040) FMC_RX1.B26@6156,1065 ; FMC_RX1.B26@6156,1065 v1(6181,1090) FMC_RX1.A25@6206,1115 ; FMC_RX1.B23@6156,1215 v1(6131,1240) FMC_RX1.B22@6156,1265 ; FMC_RX1.B23@6156,1215 v1(6181,1240) FMC_RX1.B22@6156,1265 ; FMC_RX1.B23@6156,1215 v1(6181,1190) FMC_RX1.A24@6206,1165 ; FMC_RX1.B22@6156,1265 v1(6181,1290) FMC_RX1.A21@6206,1315 ; FMC_RX1.B19@6156,1415 v1(6181,1440) FMC_RX1.B18@6156,1465 ; FMC_RX1.B19@6156,1415 v1(6181,1390) FMC_RX1.A20@6206,1365 v1(6231,1340) FMC_RX1.A21@6206,1315 ; FMC_RX1.B18@6156,1465 v1(6181,1490) FMC_RX1.A17@6206,1515 ; FMC_RX1.B7@6156,2015 v1(6181,1990) FMC_RX1.A8@6206,1965 ; FMC_RX1.B7@6156,2015 v1(6181,2040) FMC_RX1.B6@6156,2065 ; FMC_RX1.B7@6156,2015 v1(6131,2040) FMC_RX1.B6@6156,2065 ; FMC_RX1.B6@6156,2065 v1(6181,2090) FMC_RX1.A5@6206,2115 ; FMC_RX1.B2@6156,2265 v1(6181,2290) FMC_RX1.A1@6206,2315 ; FMC_RX1.A37@6206,515 v1(6231,540) FMC_RX1.A36@6206,565 ; FMC_RX1.A37@6206,515 v1(6181,540) FMC_RX1.A36@6206,565 ; FMC_RX1.A33@6206,715 v1(6181,740) FMC_RX1.A32@6206,765 ; FMC_RX1.A33@6206,715 v1(6231,740) FMC_RX1.A32@6206,765 ; FMC_RX1.A29@6206,915 v1(6181,940) FMC_RX1.A28@6206,965 ; FMC_RX1.A29@6206,915 v1(6231,940) FMC_RX1.A28@6206,965 ; FMC_RX1.A25@6206,1115 v1(6181,1140) FMC_RX1.A24@6206,1165 ; FMC_RX1.A25@6206,1115 v1(6231,1140) FMC_RX1.A24@6206,1165 ; FMC_RX1.A17@6206,1515 v1(6181,1540) FMC_RX1.A16@6206,1565 ; FMC_RX1.A17@6206,1515 v1(6231,1540) FMC_RX1.A16@6206,1565 ; FMC_RX1.A9@6206,1915 v1(6181,1940) FMC_RX1.A8@6206,1965 ; FMC_RX1.A9@6206,1915 v1(6231,1940) FMC_RX1.A8@6206,1965 ; FMC_RX1.A5@6206,2115 v1(6231,2140) FMC_RX1.A4@6206,2165 ; FMC_RX1.A5@6206,2115 v1(6181,2140) FMC_RX1.A4@6206,2165
  Bottom Layer - L10 w19.5: v1(3324,1140) 3359.63,1140 ; C2.2@3329.31,1210.67 R3.1@3329.32,1254.36 ; R12.1@3359.63,1122 C11.2@3359.63,1158
  Bottom Layer - L10 w19.68: C272.1@923.07,1160 v6(945.52,1160) ; C291.2@1063.79,1313.34 C292.1@1063.79,1346.97 ; 1063.79,1330.16 v5(1087,1330.16) ; v1(2551.68,1620.81) v1(2551.68,1736.18)
  Bottom Layer - L10 w21.46: C266.2@826.54,1196.02 C266.2@847.92,1196.02 ; v6(826.46,1464.29) C268.2@847.92,1464.29 ; C267.1@919.38,1196.02 C267.1@940.76,1196.02 ; C269.1@919.38,1464.29 C269.1@940.76,1464.29 ; v6(955.37,1271.2) v6(955.37,1296.66) ; v6(955.37,1363.65) v6(955.37,1389.12)
  Bottom Layer - L10 w31.5: R49.1@3882.56,2037.44 4016.93,2037.44 ; v9(3926.38,2038.62) v9(3926.38,1991.38) 4016.93,1991.38 ; v9(3973.62,1991.38) v9(3973.62,2038.62) ; C128.2@4016.93,1940 C127.2@4016.93,2090 ; R77.1@4670.56,2037.44 4804.93,2037.44 ; v9(4714.38,2038.62) v9(4714.38,1991.38) 4804.93,1991.38 ; v9(4761.62,1991.38) v9(4761.62,2038.62) ; C161.2@4804.93,1940 C160.2@4804.93,2090
  other v1: 2115.45,36.28 2115.45,73.49 1614.24,76.96 1651.46,76.96 1688.67,76.96 2115.45,110.7 1614.24,112.01 1651.46,112.01 1688.67,112.01 3759.5,251 3389.29,335.96 5273.94,420 4719,517.87 4691.26,622 1965.28,924.59 680.41,953.59 628.84,974.96 731.98,974.96 2333.5,976.44 2433.5,976.44 1812.02,984.2 1894.65,984.2 607.48,1026.53 753.34,1026.53 3077.31,1040 3594.05,1040 3941.85,1040 3991.85,1040 4041.85,1040 4091.85,1040 4141.85,1040 4191.85,1040 4241.85,1040 4291.85,1040 4341.85,1040 4391.85,1040 4441.85,1040 4491.85,1040 4541.85,1040 4641.85,1040 4691.85,1040 4741.85,1040 4791.85,1040 4841.85,1040 4891.85,1040 4941.85,1040 5470.56,1040 618.77,1066.82 742.05,1066.82 3008.06,1090 3888.97,1090 4391.47,1090 4442.53,1090 4891.85,1090 4941.85,1090 4993.03,1090 651.02,1093.28 709.8,1093.28 1267.73,1103.87 3063,1115 3604.53,1140 3892,1140 3942,1140 4391.47,1140 4442.53,1140 4891.85,1140 4941.85,1140 4991.85,1140 651.02,1143.28 709.8,1143.28 2109,1168.84 3604.53,1190 3892,1190 3942,1190 4391.47,1190 4442.53,1190 4891.85,1190 4941.85,1190 4991.85,1190 5194,1190 5253,1190 651.02,1193.28 709.8,1193.28 3068,1215 2109,1215.89 2199,1227.89 1084,1229 1134,1229 1184,1229 1234,1229 1284,1229 3324,1232.52 1034,1238 3892,1240 4391.47,1240 4417,1240 4442.53,1240 4891.85,1240 4991.85,1240 5194,1240 5253,1240 716,1243.28 764,1260 2199,1274.95 1300,1277.32 1350,1277.32 1005,1279 2109,1286.95 3940.15,1290 4417,1290 4891.85,1290 1389,1292 2109,1334 4891.85,1340 4941.85,1340 2199,1346 1389,1368.32 1005,1381.31 1300,1383 1350,1383 4212.39,1390 4262.39,1390 4312.39,1390 4521.61,1390 4571.61,1390 4621.61,1390 5178,1390 5312,1390 2199,1393.06 2992.31,1397.5 764,1400.31 2109,1405.06 716,1417.04 1034,1422.31 1084,1431.31 1134,1431.31 1184,1431.31 1234,1431.31 1284,1431.31 4212.39,1440 4262.39,1440 4312.39,1440 4521.61,1440 4571.61,1440 4621.61,1440 5178,1440 5312,1440 2109,1452.11 2199,1464.11 651.02,1467.04 709.8,1467.04 4212.39,1490 4262.39,1490 4312.39,1490 4347.26,1490 4382.13,1490 4417,1490 4451.87,1490 4486.74,1490 4521.61,1490 4571.61,1490 4621.61,1490 2199,1511.17 651.02,1517.04 709.8,1517.04 2805.65,1540 4212.39,1540 4262.39,1540 4312.39,1540 4347.26,1540 4382.13,1540 4417,1540 4451.87,1540 4486.74,1540 4521.61,1540 4571.61,1540 4621.61,1540 2191.47,1544.09 1030.65,1545.95 1395.57,1562.43 651.02,1567.04 709.8,1567.04 1030.65,1574.95 2882.55,1584.68 2999.92,1584.68 4212.39,1590 4262.39,1590 4312.39,1590 4521.61,1590 4571.61,1590 4621.61,1590 618.77,1593.49 742.05,1593.49 2419.82,1603.5 1030.65,1603.95 1400.82,1618.62 2065,1619 2488.05,1620.81 901.58,1624.95 926.58,1624.95 5602.5,1633.3 5627.8,1633.3 607.48,1633.79 753.34,1633.79 1938.64,1637 4212.39,1640 4262.39,1640 4312.39,1640 4521.61,1640 4571.61,1640 4621.61,1640 2145.54,1653.5 1400.82,1660.67 1503,1668.13 3244,1679.37 3538.47,1679.37 5602.5,1684.2 5627.8,1684.2 628.84,1685.36 731.98,1685.36 4097,1690 4147,1690 4687,1690 4737,1690 680.41,1706.72 3173.33,1712.23 3106.33,1721.1 1829.81,1723.61 1876.86,1723.61 2178.54,1736.5 2488.05,1736.18 4097,1740 4147,1740 4197,1740 4345,1740 4393,1740 4488,1740 4538,1740 4637,1740 4687,1740 4737,1740 1555.91,1743.81 2022.36,1788.53 2300,1790 2393,1790 5538.38,1790 1756.96,1809.5 1811.01,1809.5 1686.92,1811 1500.95,1837.32 1594.58,1837.31 1719.3,1838.05 2022.36,1840 3051.65,1840 3473.91,1840 2177,1841.77 2552.68,1843.81 3051.65,1890 4499.56,1890 2799.35,1940 2989.12,1940 3417,1940 2552.68,1990 944.21,2048.5 991.9,2048.5 2023.06,2119.97 928.69,2141.68 3749.44,2150 3906.69,2150 4537.44,2150 4694.69,2150 2023.06,2174.02 2881.31,2179.37 2861.63,2235.37 3422,2242.56 1339.1,2257 3446.12,2292.5 4091.79,2334.81 4225.46,2334.81 4359.13,2334.81 3247.88,2341.5 3446.12,2341.5 3494,2372.62 3670.68,2390.44 3186.44,2406.01 4091.79,2436 4225.46,2436 4359.13,2436 4613,2436 4663,2436 3962.68,2464.56 5015.5,2486.37 3962.68,2511.44 4091.79,2537.19 4225.46,2537.19 4359.13,2537.19 4759,2563.95 4762.56,2612
  other v2: 1577.75,1192.36 1626.96,1192.36 1676.17,1192.36 1725.39,1192.36 1774.6,1192.36 1823.81,1192.36 1873.02,1192.36 1577.75,1241.57 1626.96,1241.57 1676.17,1241.57 1725.39,1241.57 1774.6,1241.57 1823.81,1241.57 1873.02,1241.57 1577.75,1290.79 1626.96,1290.79 1676.17,1290.79 1725.39,1290.79 1774.6,1290.79 1823.81,1290.79 1873.02,1290.79 1577.75,1340 1626.96,1340 1676.17,1340 1725.39,1340 1774.6,1340 1823.81,1340 1873.02,1340 1577.75,1389.21 1626.96,1389.21 1676.17,1389.21 1725.39,1389.21 1774.6,1389.21 1823.81,1389.21 1873.02,1389.21 1577.75,1438.43 1626.96,1438.43 1676.17,1438.43 1725.39,1438.43 1774.6,1438.43 1823.81,1438.43 1873.02,1438.43 1577.75,1487.64 1626.96,1487.64 1676.17,1487.64 1725.39,1487.64 1774.6,1487.64 1823.81,1487.64 1873.02,1487.64 2854.87,1740 2894.24,1740 2933.61,1740 2854.87,1790 2933.61,1790 2854.87,1840 2894.24,1840 2933.61,1840 1599.34,2015.5 1656.82,2015.5 1714.3,2015.5 1771.78,2015.5 1554.06,2060.78 1599.34,2060.78 1656.82,2060.78 1714.3,2060.78 1771.78,2060.78 1817.06,2060.78 1554.06,2118.26 1599.34,2118.26 1656.82,2118.26 1714.3,2118.26 1771.78,2118.26 1817.06,2118.26 1554.06,2175.74 1599.34,2175.74 1656.82,2175.74 1714.3,2175.74 1771.78,2175.74 1817.06,2175.74 1554.06,2233.22 1599.34,2233.22 1656.82,2233.22 1714.3,2233.22 1771.78,2233.22 1817.06,2233.22 1599.34,2278.5 1656.82,2278.5 1714.3,2278.5 1771.78,2278.5 3777.3,2448.63 3816.68,2448.63 3856.05,2448.63 3777.3,2488 3816.68,2488 3856.05,2488 3777.3,2527.37 3816.68,2527.37 3856.05,2527.37
  other v4: 5334.98,1190 5360.99,1190 5387,1190 5413.01,1190 5439.02,1190 5334.98,1240 5360.99,1240 5387,1240 5413.01,1240 5439.02,1240 29,1619.16 100,1619.16 171,1619.16 29,1696.16 100,1696.16 171,1696.16 29,1964.16 100,1964.16 171,1964.16 29,2041.16 100,2041.16 171,2041.16 29,2119.16 100,2119.16 171,2119.16 29,2196.16 100,2196.16 171,2196.16 29,2464.16 100,2464.16 171,2464.16 29,2541.16 100,2541.16 171,2541.16
  other v5: 214.59,1090.99 272.59,1090.99 118.73,1205.99 118.73,1309.99 1140.75,1330.16 1217.44,1330.16
  other v6: 824.46,1196.02 849.92,1196.02 917.3,1196.02 942.76,1196.02 849.92,1464.29 917.3,1464.29 942.76,1464.29
  other v10: 2108.28,749.51 2068.91,796.76 2108.28,796.76 2147.65,796.76 2108.28,844
GND2: C118.2 C119.2 C131.2 C132.2 C133.2 C134.2 C135.2 C136.2 C137.2 C138.2 C139.2 C140.2 C141.2 C142.2 C200.2 C201.2 C205.2 C210.2 C211.2 C212.1 C214.2 L23.1 R67.1 R112.1 U13.1 U13.5 U13.10 U13.11 U13.13 U13.15 U13.25 U13.35 U13.47 U13.51 U14.2 U14.4 U15.5 USB.5 USB.6 USB.7 USB.8 USB.9 | length 1322.1
  Top Layer - L1 w10: v1(3124.5,645.48) 3134.34,635.64 U13.1@3178.97,635.64 ; U13.15@3178.97,360.05 v1(3233,360.05) ; U13.13@3178.97,399.42 v1(3233,399.42) ; U13.11@3178.97,438.79 3223.59,438.79 v1(3233.44,448.63) 3223.59,458.47 U13.10@3178.97,458.47 ; U13.5@3178.97,556.9 v1(3233,556.9) ; v1(3397.47,215.03) 3407.31,224.87 U13.25@3407.31,269.5 ; v1(3505.74,652.04) U13.51@3505.74,706.5 ; v1(3561.51,379.73) U13.35@3615.98,379.73 C134.2@3670.44,379.73 ; v1(3561.51,615.95) U13.47@3615.98,615.95 ; C134.2@3670.44,381.5 3676.5,381.5 v1(3683,375)
  Top Layer - L1 w16.5: v1(3033,947.84) 3033,932.66 C137.2@3039.66,926 C135.2@3087.28,926 3083,930.28 v1(3083,947.84) ; C133.2@3077.46,419.1 3077.46,404.7 v1(3083,399.16) ; C140.2@3077.46,468.32 3077.46,453.91 v1(3083,448.37) ; C142.2@3077.46,566.74 3077.46,581.14 v1(3083,586.68) ; C136.2@3233,808.01 v1(3233,829.07) ; C118.2@3344.72,215.03 v1(3365.77,215.03) ; v1(3433.3,801.51) C132.2@3433.3,781.24 C214.2@3489.6,781.24 v1(3489.6,801.51) ; C119.2@3572.46,210.03 v1(3593.52,210.03) ; C131.2@3686.44,571.41 v1(3686.44,592.47)
  Top Layer - L1 w19.5: USB.5@330.71,719.44 v1(387.98,719.45)
  Top Layer - L1 w24: v1(2989.74,603.08) R67.1@3018.47,603.08
  Bottom Layer - L10 w16.5: v1(275.94,670.86) 320.38,670.86 v1(329.24,662) ; v1@3561.51,616.47 3544.68,616.47 U15.5@3544.68,605.39 3599.17,605.39 C205.2@3610,594.56
  Bottom Layer - L10 w18: v1(3433.3,801.51) 3433.3,841.38 C212.1@3437.91,846
  Bottom Layer - L10 w24: C139.2@3076.19,477.1 3083,470.29 v1(3083,448.37) ; v1(3083,586.68) 3102.32,606 C141.2@3105.44,606
  other v1: 3696.5,251 2978.91,300.8 110.24,607.24 326.77,607.24 181.46,633.46 256.26,775.86 3461.45,781.24 3633,789.7 138.86,839 110.24,957.63 326.77,957.63
LMK04828_CSB: R68.1 R69.1 R98.1 R104.2 U6.18 | length 3453.2
  Top Layer - L1 w8: U6.18@1858.79,2019.05 1903.95,2019.05 2083,1840 v1(2113,1840) ; R104.2@3960.44,398 R98.1@3960.44,440
  Top Layer - L1 w18: R68.1@3913,440 R98.1@3960.44,440
  Signals - L3 w4: v1(2113,1840) 2126,1827 2126,1474 2169,1431 2637,1431 2781,1287 2781,1075 2846,1010 3265,1010 3360,915 v1(3427,915)
  Signals - L6 w4: v1(3427,915) 3555,915 3578,938 3838,938 3913,863 3913,616 3969,560 3969,529 3938.56,498.56 v1(3938.56,440)
  Bottom Layer - L10 w8: v1(3938.56,440) R69.1@3960.44,440
LMK04828_RESET: FMC_RX1.J16 R122.2 U6.5 | length 4841.4
  Top Layer - L1 w9: v1(1616.66,1938.69) U6.5@1616.66,1973.77
  Signals - L6 w4: v1(1994,1890) 2019,1865 5943,1865 5956,1852 5956,1628 5943,1615 5856,1615 v3(5831,1590)
  Bottom Layer - L10 w8: v1(1616.66,1938.69) 1622.98,1945 1653,1945 1708,1890 v1(1994,1890) ; FMC_RX1.J16@5806,1565 v3(5831,1590)
  Bottom Layer - L10 w18: R122.2@1590.93,1938.69 v1(1616.66,1938.69)
LMK04828_SYNC: FMC_RX1.J15 R142.1 | length 4227.5
  Signals - L6 w4: v1(1994.55,1815) 5893,1815 5906,1802 5906,1678 5893,1665 5856,1665 v3(5831,1640)
  Bottom Layer - L10 w8: R142.1@1945.56,1843 1966.55,1843 v1(1994.55,1815) ; FMC_RX1.J15@5806,1615 v3(5831,1640)
LMK_TRF_CLK: R102.1 R115.1 R121.1 R129.2 U4.4 U6.19 | length 3794
  Top Layer - L1 w8: U6.19@1858.79,2038.73 1929.27,2038.73 2028,1940 2298,1940 2409,2051 2893.08,2051 v1(2904.08,2040) U4.4@2904.08,1884.49 ; R102.1@3953.63,240 v1(3960.44,240) R115.1@3960.44,157.56
  Signals - L3 w4: v1(2904.08,2040) 2913.92,2030.16 2913.92,1737.08 2979,1672 2979,1527 3036,1470 3036,1419 3133,1322 3257,1322 3580.5,998.5 3683.5,998.5 v1(3838,844)
  Signals - L6 w4: v1(3838,844) 3838,560.44 3863,535.44 3863,337.44 v1(3960.44,240)
  Bottom Layer - L10 w8: v1(3960.44,240) R129.2@3960.44,282
LMK_TRF_DATA: R101.1 R114.1 R120.1 R128.2 U4.3 U6.20 | length 3686
  Top Layer - L1 w8: U6.20@1858.79,2058.42 2009.42,2058.42 2041,2090 v1(2923.76,2090) U4.3@2923.76,1884.49 ; R114.1@3913,298 R128.2@3960.44,298 v1(3960.44,340)
  Signals - L3 w4: v1(2923.76,2090) 2953.29,2060.47 2953.29,1756.54 3075,1634.83 3075,1429 3143,1361 3309,1361 3612,1058 3674,1058 v1(3863,869)
  Signals - L6 w4: v1(3863,869) 3863,573 3888,548 3888,412.44 v1(3960.44,340)
LO1_N: C83.1 R34.2 U4.10 | length 266.8
  Top Layer - L1 w8: C83.1@2559.73,1883.18 R34.2@2592.05,1883.18 2602.36,1893.5 2707.68,1893.5 2760.12,1841.05 2789.86,1841.05 2791.7,1839.21 U4.10@2799.75,1839.21
LO1_P: C75.1 R27.2 U4.9 | length 266.8
  Top Layer - L1 w8: C75.1@2559.73,1919.81 R27.2@2592.05,1919.81 2602.36,1909.5 2714.3,1909.5 2766.75,1857.05 2789.86,1857.05 2791.7,1858.9 U4.9@2799.75,1858.9
LO2_N: LO2_N.1 U4.11 | length 166.2
  Top Layer - L1 w8: LO2_N.1@2641.05,1833.99 2652.04,1823 2731.8,1823 2737.12,1817.68 2789.86,1817.68 2791.7,1819.53 U4.11@2799.75,1819.53
LO2_P: LO2_P.1 U4.12 | length 166.2
  Top Layer - L1 w8: LO2_P.1@2641.05,1796.01 2652.04,1807 2725.18,1807 2730.49,1801.68 2789.86,1801.68 2791.7,1799.84 U4.12@2799.75,1799.84
LO3_N: LO3_N.1 U4.14 | length 153.6
  Top Layer - L1 w8: LO3_N.1@2691.32,1728 2681,1738.31 2681,1754.63 2688.69,1762.31 2789.86,1762.31 2791.7,1760.47 U4.14@2799.75,1760.47
LO3_P: LO3_P.1 U4.13 | length 180.1
  Top Layer - L1 w8: LO3_P.1@2654.69,1728 2665,1738.32 2665,1761.26 2682.06,1778.32 2789.86,1778.32 2791.7,1780.16 U4.13@2799.75,1780.16
LO4_N: C84.1 R35.2 U4.15 | length 267.8
  Top Layer - L1 w8: C84.1@2558.73,1696.81 R35.2@2591.05,1696.81 2601.36,1686.5 2707.68,1686.5 2760.12,1738.95 2789.86,1738.95 2791.7,1740.79 U4.15@2799.75,1740.79
LO4_P: C76.1 R28.2 U4.16 | length 267.8
  Top Layer - L1 w8: C76.1@2558.73,1660.18 R28.2@2591.05,1660.18 2601.36,1670.5 2714.3,1670.5 2766.75,1722.94 2789.86,1722.94 2791.7,1721.1 U4.16@2799.75,1721.1
NCO_0: NCO.1 R6.2 R7.1 R136.1 | length 502.4
  Top Layer - L1 w8: v1(2145.2,1211.93) 2267.13,1090 NCO.1@2333.5,1090 2383.5,1140 R136.1@2383.5,1274.44
  Bottom Layer - L10 w8: R6.2@2333.5,1031.56 NCO.1@2333.5,1090
NCO_1: NCO.3 R5.2 R8.1 R137.1 | length 669.5
  Top Layer - L1 w8: NCO.3@2433.5,1090 2483.5,1140 R137.1@2483.5,1276
  Bottom Layer - L10 w8: R8.1@2055.2,1152.88 2073.27,1134.81 2388.69,1134.81 NCO.3@2433.5,1090 R5.2@2433.5,1031.56
NCO_2: NCO.5 R4.2 R9.1 R138.1 | length 1227.9
  Top Layer - L1 w8: v1(1813.86,1010.18) 1823.67,1020 2463.5,1020 NCO.5@2533.5,1090 ; R138.1@2952.94,1040 R4.2@2952.94,1090
  Bottom Layer - L10 w8: NCO.5@2533.5,1090 2574.5,1049 2929,1049 v1(2938,1040)
Net1V2ADC_INT_2: 1V2ADC_INT.2 C172.1 R83.2 U10.5 U10.6 U10.7 U10.8 | length 97.4
  Bottom Layer - L10 w51: 1V2ADC_INT.2@3892.26,2305 3899.35,2297.91 R83.2@3899.35,2210.56
Net1V2ADC_LDO_1: 1V2ADC_LDO.1 C185.1 C195.1 R84.1 R85.2 U10.1 U10.18 U10.19 U10.20 | length 97.4
  Bottom Layer - L10 w51: 1V2ADC_LDO.1@3585.27,2469 3592.35,2476.09 R84.1@3592.35,2563.44
  other v1: 3670.68,2445.56
Net1V2ADC_LDO_2: 1V2ADC_LDO.2 L15.1 L16.1 R84.2 | length 279.6
  Top Layer - L1 w37: L15.1@3303,2469 L16.1@3391,2469 1V2ADC_LDO.2@3485.27,2469
  Bottom Layer - L10 w51: R84.2@3478.18,2563.44 3478.18,2476.09 1V2ADC_LDO.2@3485.27,2469
Net1V9ADC_1: 1V9ADC.1 C192.1 C198.1 C204.1 R92.1 R93.2 U11.4 | length 377.2
  Top Layer - L1 w37: U11.4@4615.22,2502.93 1V9ADC.1@4847,2502.93
  Bottom Layer - L10 w24: v1(4711,2508.83) v1(4759,2508.83)
  Bottom Layer - L10 w51: 1V9ADC.1@4847,2502.93 4854.09,2495.84 R92.1@4941.44,2495.84
Net1V9ADC_2: 1V9ADC.2 L18.1 R92.2 | length 197.9
  Top Layer - L1 w31.5: 1V9ADC.2@4847,2602.93 L18.1@4947.5,2602.93
  Bottom Layer - L10 w51: 1V9ADC.2@4847,2602.93 4854.09,2610.02 R92.2@4941.44,2610.02
Net1V9INT_2: 1V9INT.2 C196.1 R95.2 U11.1 U11.2 | length 487
  Top Layer - L1 w37: U11.1@4615.22,2302.14 4730.07,2302.14 1V9INT.2@4796,2369.07 U11.2@4615.22,2369.07
  Bottom Layer - L10 w51: 1V9INT.2@4796,2369.07 4803.09,2376.16 R95.2@4890.44,2376.16
Net3P3USB_1: 3P3USB.1 C139.1 C140.1 L24.2 U13.9 | length 301.4
  Top Layer - L1 w10: v1(3124.5,468.31) 3134.34,478.16 U13.9@3178.97,478.16
  Top Layer - L1 w16.5: C140.1@3103.44,468.32 v1(3124.5,468.31)
  Bottom Layer - L10 w8: 3P3USB.1@3005,419 3065,419 3071,425 3094,425 3107,438 3107,450.81 v1(3124.5,468.31)
  Bottom Layer - L10 w24: v1(3124.5,468.31) 3147.18,491 L24.2@3189.5,491
Net5VDC_1: 5VDC.1 S1.2 | length 581.5
  Bottom Layer - L10 w50: 5VDC.1@564.37,235 955.2,235 S1.2@1090,100.2
Net5VDC_2: 5VDC.2 LF7.1 | length 1487.5
  Bottom Layer - L10 w50: 5VDC.2@303.15,235 329.15,261 415,261 529.51,375.51 1361.79,375.51 1479,258.31 1479,166.89 1406.6,94.49 LF7.1@1395.55,94.49
Net12V_1: 12V.1 R94.1 | length 88.2
  Top Layer - L1 w25: R94.1@5308,342.15 5333,367.15 12V.1@5333,420
NetC2_1: C2.1 D2.1 R3.2 U1.3 | length 187.3
  Bottom Layer - L10 w8: D2.1@3243.95,1165 3323.02,1165 C2.1@3368.68,1210.67
  Bottom Layer - L10 w19.5: C2.1@3368.68,1210.67 R3.2@3368.69,1254.36
  other v1: 3374,1232.52
NetC7_2: C7.2 U2.33 | length 139.9
  Bottom Layer - L10 w8: U2.33@1863.18,1532.91 1861.34,1534.76 1861.34,1664.32 C7.2@1866.84,1669.81
NetC8_1: C8.1 D4.1 R11.2 U1.5 | length 222.2
  Top Layer - L1 w8: D4.1@3243.95,1115 3263.95,1095 3305,1095 3324,1076 U1.5@3324,1047.48 C8.1@3324,985 R11.2@3324,950
NetC9_2: C9.2 U2.32 | length 139.9
  Bottom Layer - L10 w8: C9.2@1839.84,1669.81 1845.34,1664.31 1845.34,1534.76 U2.32@1843.5,1532.91
NetC10_2: C10.2 U2.36 | length 229.9
  Bottom Layer - L10 w8: U2.36@1918.3,1477.8 1920.14,1479.64 2139.7,1479.64 C10.2@2145.2,1474.14
NetC11_1: C11.1 R1.1 R12.2 U1.2 U1.6 | length 281.1
  Top Layer - L1 w19.5: U1.6@3374,1047.48 3374,1115 v1(3399,1140) 3424,1165 U1.2@3424,1232.52
  Bottom Layer - L10 w19.5: R12.2@3399,1122 C11.1@3399,1158 ; v1(3399,1140) R1.1@3438.31,1140
NetC12_2: C12.2 U2.35 | length 229.9
  Bottom Layer - L10 w8: U2.35@1918.3,1497.48 1920.14,1495.64 2139.7,1495.64 C12.2@2145.2,1501.14
NetC13_2: C13.2 U2.39 | length 139.9
  Bottom Layer - L10 w8: U2.39@1918.3,1418.74 1920.14,1420.58 2049.7,1420.58 C13.2@2055.2,1415.08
